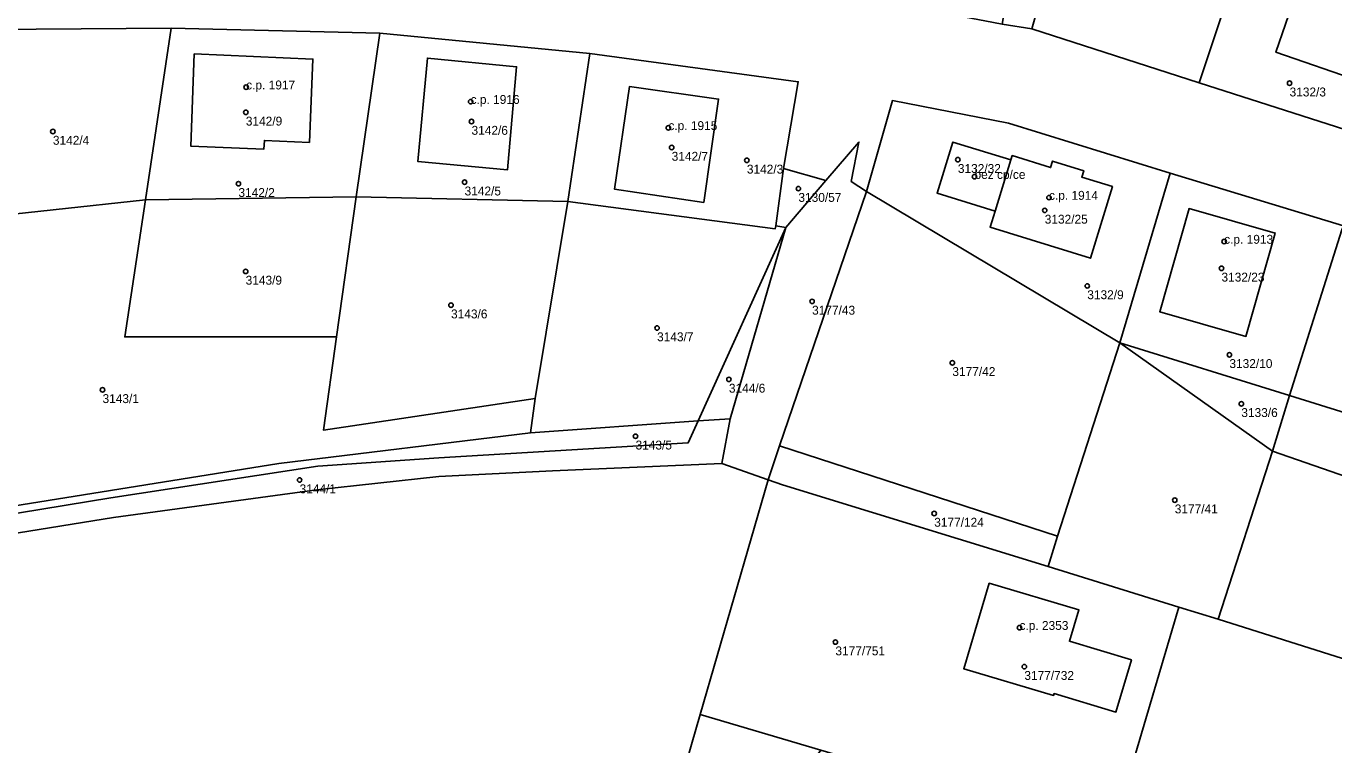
# Model space of a CAD drawing. Extents: x -878211 to -870363, y -1058464 to -1052522.
# Drawn here: x -874670.5 to -874523.6, y -1056692 to -1056611.2 of the extents above; entities that cross this region are included whole.
import ezdxf

# ---------------------------------------------------------------- set-up
doc = ezdxf.new("R2010")
doc.units = 0
for name, color, linetype in [('Definiční body', 7, 'Continuous'), ('Polygon budovy', 7, 'Continuous'), ('Polygon parcely', 7, 'Continuous')]:
    doc.layers.add(name, color=color, linetype=linetype)

msp = doc.modelspace()

# ---------------------------------------------------------------- linework, layer by layer
at = {"layer": 'Definiční body'}
for centre in [(-874645.82, -1056618.01994), (-874528.58, -1056617.56994), (-874620.6, -1056619.64994), (-874645.86, -1056620.83994), (-874667.54, -1056622.99994), (-874620.5, -1056621.87994), (-874598.38, -1056622.58994), (-874598.01, -1056624.79994), (-874589.56, -1056626.23994), (-874565.85, -1056626.16994), (-874646.69, -1056628.86994), (-874621.28, -1056628.69994), (-874563.98, -1056628.07994), (-874583.77, -1056629.41994), (-874556.09, -1056631.86994), (-874555.61, -1056630.42994), (-874535.93, -1056635.36994), (-874645.88, -1056638.72994), (-874536.23, -1056638.37994), (-874551.31, -1056640.35994), (-874582.23, -1056642.09994), (-874622.8, -1056642.51994), (-874599.65, -1056645.08994), (-874566.47, -1056648.99994), (-874535.34, -1056648.09994), (-874591.58, -1056650.86994), (-874661.96, -1056652.03994), (-874534, -1056653.60994), (-874602.07, -1056657.25994), (-874639.82, -1056662.17994), (-874541.48, -1056664.43994), (-874568.51, -1056665.93994), (-874558.93, -1056678.77994), (-874579.61, -1056680.39994), (-874558.38, -1056683.15994)]:
    msp.add_circle(centre, 0.25, dxfattribs=at)
at = {"layer": 'Polygon budovy'}
for points in [[(-874530.12, -1056614.09), (-874520.57, -1056617.36), (-874517.32, -1056607.88), (-874526.88, -1056604.61)], [(-874651.65, -1056614.27), (-874652.04, -1056624.63), (-874643.82, -1056624.98), (-874643.77, -1056624), (-874638.72, -1056624.23), (-874638.32, -1056614.85)], [(-874626.52, -1056626.39), (-874616.46, -1056627.32), (-874615.43, -1056615.72), (-874625.45, -1056614.75)], [(-874604.43, -1056629.49), (-874594.41, -1056630.97), (-874592.73, -1056619.36), (-874602.76, -1056617.95)], [(-874568.19, -1056629.94), (-874561.66, -1056631.95), (-874559.9, -1056626.17), (-874566.41, -1056624.18)], [(-874551.93, -1056628.13), (-874551.71, -1056627.42), (-874555.21, -1056626.33), (-874555.43, -1056627.05), (-874559.75, -1056625.71), (-874559.9, -1056626.17), (-874561.66, -1056631.95), (-874562.23, -1056633.77), (-874550.96, -1056637.25), (-874548.49, -1056629.19)], [(-874543.17, -1056643.26), (-874533.48, -1056646.03), (-874530.19, -1056634.41), (-874539.87, -1056631.66)], [(-874565.19, -1056683.4), (-874555.1, -1056686.39), (-874555.04, -1056686.19), (-874548.09, -1056688.26), (-874546.36, -1056682.4), (-874553.31, -1056680.3), (-874552.25, -1056676.78), (-874562.33, -1056673.78)]]:
    msp.add_lwpolyline(points, close=True, dxfattribs=at)
at = {"layer": 'Polygon parcely'}
for points in [[(-874546.14, -1056592.16), (-874550.37, -1056590.73), (-874559.16, -1056587.83), (-874559.58, -1056590.6), (-874559.85, -1056592.38), (-874557.82, -1056592.74), (-874560.87, -1056610.94), (-874557.53, -1056611.45), (-874553.66, -1056597.86), (-874552.14, -1056593.1), (-874545.38, -1056592.43)], [(-874545.38, -1056592.43), (-874552.14, -1056593.1), (-874553.66, -1056597.86), (-874557.53, -1056611.45), (-874538.75, -1056617.53), (-874531.91, -1056597.08)], [(-874519.44, -1056623.7), (-874513.29, -1056603.18), (-874527.34, -1056598.5), (-874531.91, -1056597.08), (-874538.75, -1056617.53)], [(-874526.88, -1056604.61), (-874530.12, -1056614.09), (-874520.57, -1056617.36), (-874517.32, -1056607.88)], [(-874526.88, -1056604.61), (-874517.32, -1056607.88), (-874520.57, -1056617.36), (-874530.12, -1056614.09)], [(-874654.24, -1056611.37), (-874674.5, -1056611.53), (-874677.93, -1056632.92), (-874657.15, -1056630.68)], [(-874630.82, -1056611.95), (-874654.24, -1056611.37), (-874657.15, -1056630.68), (-874633.46, -1056630.33)], [(-874609.69, -1056630.88), (-874607.22, -1056614.22), (-874630.82, -1056611.95), (-874633.46, -1056630.33)], [(-874651.65, -1056614.27), (-874652.04, -1056624.63), (-874643.82, -1056624.98), (-874643.77, -1056624), (-874638.72, -1056624.23), (-874638.32, -1056614.85)], [(-874651.65, -1056614.27), (-874638.32, -1056614.85), (-874638.72, -1056624.23), (-874643.77, -1056624), (-874643.82, -1056624.98), (-874652.04, -1056624.63)], [(-874625.45, -1056614.75), (-874615.43, -1056615.72), (-874616.46, -1056627.32), (-874626.52, -1056626.39)], [(-874625.45, -1056614.75), (-874626.52, -1056626.39), (-874616.46, -1056627.32), (-874615.43, -1056615.72)], [(-874609.69, -1056630.88), (-874586.37, -1056633.94), (-874586.32, -1056633.6), (-874585.46, -1056627.16), (-874583.78, -1056617.4), (-874607.22, -1056614.22)], [(-874594.41, -1056630.97), (-874604.43, -1056629.49), (-874602.76, -1056617.95), (-874592.73, -1056619.36)], [(-874594.41, -1056630.97), (-874592.73, -1056619.36), (-874602.76, -1056617.95), (-874604.43, -1056629.49)], [(-874542.01, -1056627.68), (-874560.17, -1056622.07), (-874573.21, -1056619.53), (-874576.13, -1056629.76), (-874547.67, -1056646.74)], [(-874587.18, -1056662.15), (-874585.89, -1056658.34), (-874576.13, -1056629.76), (-874577.84, -1056628.61), (-874576.97, -1056624.18), (-874580.67, -1056628.5), (-874585.2, -1056633.78), (-874591.42, -1056655.29), (-874592.37, -1056660.31)], [(-874555.43, -1056627.05), (-874555.21, -1056626.33), (-874551.71, -1056627.42), (-874551.93, -1056628.13), (-874548.49, -1056629.19), (-874550.96, -1056637.25), (-874562.23, -1056633.77), (-874561.66, -1056631.95), (-874568.19, -1056629.94), (-874566.41, -1056624.18), (-874559.9, -1056626.17), (-874559.75, -1056625.71)], [(-874559.9, -1056626.17), (-874566.41, -1056624.18), (-874568.19, -1056629.94), (-874561.66, -1056631.95)], [(-874559.9, -1056626.17), (-874561.66, -1056631.95), (-874562.23, -1056633.77), (-874550.96, -1056637.25), (-874548.49, -1056629.19), (-874551.93, -1056628.13), (-874551.71, -1056627.42), (-874555.21, -1056626.33), (-874555.43, -1056627.05), (-874559.75, -1056625.71)], [(-874585.46, -1056627.16), (-874586.32, -1056633.6), (-874585.2, -1056633.78), (-874580.67, -1056628.5)], [(-874547.67, -1056646.74), (-874528.58, -1056652.68), (-874522.69, -1056634.07), (-874522.52, -1056633.61), (-874542.01, -1056627.68)], [(-874576.13, -1056629.76), (-874585.89, -1056658.34), (-874554.65, -1056668.48), (-874547.67, -1056646.74)], [(-874637.15, -1056656.56), (-874635.67, -1056646.07), (-874659.47, -1056646.09), (-874657.15, -1056630.68), (-874677.93, -1056632.92), (-874683.06, -1056666.87), (-874642.16, -1056660.32), (-874613.87, -1056656.86), (-874613.33, -1056653.02)], [(-874657.15, -1056630.68), (-874659.47, -1056646.09), (-874635.67, -1056646.07), (-874633.46, -1056630.33)], [(-874633.46, -1056630.33), (-874635.67, -1056646.07), (-874637.15, -1056656.56), (-874613.33, -1056653.02), (-874609.69, -1056630.88)], [(-874586.32, -1056633.6), (-874586.37, -1056633.94), (-874609.69, -1056630.88), (-874613.33, -1056653.02), (-874613.87, -1056656.86), (-874595.04, -1056655.54), (-874585.2, -1056633.78)], [(-874539.87, -1056631.66), (-874543.17, -1056643.26), (-874533.48, -1056646.03), (-874530.19, -1056634.41)], [(-874539.87, -1056631.66), (-874530.19, -1056634.41), (-874533.48, -1056646.03), (-874543.17, -1056643.26)], [(-874585.2, -1056633.78), (-874595.04, -1056655.54), (-874591.42, -1056655.29)], [(-874509.49, -1056658.62), (-874503.66, -1056639.59), (-874522.52, -1056633.61), (-874522.69, -1056634.07), (-874528.58, -1056652.68)], [(-874541.03, -1056676.46), (-874536.59, -1056677.84), (-874530.51, -1056658.93), (-874547.67, -1056646.74), (-874554.65, -1056668.48), (-874555.7, -1056671.89)], [(-874547.67, -1056646.74), (-874530.51, -1056658.93), (-874528.58, -1056652.68)], [(-874528.58, -1056652.68), (-874530.51, -1056658.93), (-874511.82, -1056665.4), (-874509.49, -1056658.62)], [(-874595.04, -1056655.54), (-874613.87, -1056656.86), (-874642.16, -1056660.32), (-874683.06, -1056666.87), (-874694.93, -1056668.88), (-874694.57, -1056669.7), (-874661.04, -1056664.2), (-874637.76, -1056660.62), (-874624.16, -1056659.67), (-874596.15, -1056657.99)], [(-874637.88, -1056663.27), (-874624.16, -1056661.77), (-874611.39, -1056661.13), (-874592.37, -1056660.31), (-874591.42, -1056655.29), (-874595.04, -1056655.54), (-874596.15, -1056657.99), (-874624.16, -1056659.67), (-874637.76, -1056660.62), (-874661.04, -1056664.2), (-874694.57, -1056669.7), (-874692.18, -1056677.02), (-874684.42, -1056670.21), (-874660.73, -1056666.41)], [(-874555.7, -1056671.89), (-874554.65, -1056668.48), (-874585.89, -1056658.34), (-874587.18, -1056662.15), (-874585.54, -1056662.73)], [(-874536.59, -1056677.84), (-874517.53, -1056683.84), (-874511.82, -1056665.4), (-874530.51, -1056658.93)], [(-874556.32, -1056699.93), (-874548.64, -1056702.2), (-874541.03, -1056676.46), (-874555.7, -1056671.89), (-874585.54, -1056662.73), (-874587.18, -1056662.15), (-874594.8, -1056688.54), (-874581.25, -1056692.55)], [(-874562.33, -1056673.78), (-874552.25, -1056676.78), (-874553.31, -1056680.3), (-874546.36, -1056682.4), (-874548.09, -1056688.26), (-874555.04, -1056686.19), (-874555.1, -1056686.39), (-874565.19, -1056683.4)], [(-874562.33, -1056673.78), (-874565.19, -1056683.4), (-874555.1, -1056686.39), (-874555.04, -1056686.19), (-874548.09, -1056688.26), (-874546.36, -1056682.4), (-874553.31, -1056680.3), (-874552.25, -1056676.78)], [(-874520.36, -1056710.57), (-874519.51, -1056707.69), (-874514.47, -1056705.1), (-874517.18, -1056699.85), (-874512.89, -1056685.34), (-874517.53, -1056683.84), (-874536.59, -1056677.84), (-874541.03, -1056676.46), (-874548.64, -1056702.2)], [(-874581.25, -1056692.55), (-874594.8, -1056688.54), (-874601.43, -1056711.5), (-874596.25, -1056713.03)]]:
    msp.add_lwpolyline(points, close=True, dxfattribs=at)
for points in [[(-874519.44, -1056623.7), (-874538.75, -1056617.53), (-874557.53, -1056611.45), (-874560.87, -1056610.94), (-874562.84, -1056610.56), (-874582.56, -1056606.78), (-874585.79, -1056606.36), (-874602.05, -1056603.32), (-874622.11, -1056601.39), (-874640.68, -1056600.17), (-874659.41, -1056600.63), (-874675.1, -1056600.84)], [(-874674.5, -1056611.53), (-874654.24, -1056611.37), (-874630.82, -1056611.95), (-874607.22, -1056614.22), (-874583.78, -1056617.4), (-874585.46, -1056627.16), (-874580.67, -1056628.5), (-874576.97, -1056624.18), (-874577.84, -1056628.61), (-874576.13, -1056629.76), (-874573.21, -1056619.53), (-874560.17, -1056622.07), (-874542.01, -1056627.68), (-874522.52, -1056633.61), (-874503.66, -1056639.59), (-874484.66, -1056645.64), (-874465.47, -1056651.46), (-874446.38, -1056657.11), (-874427.04, -1056662.88), (-874410.86, -1056667.5), (-874394.94, -1056671.52)], [(-874571.25, -1056835.31), (-874572.2, -1056826.32), (-874576.45, -1056826.41), (-874578.08, -1056824.19), (-874578.76, -1056805.25), (-874579.46, -1056785.71), (-874588.31, -1056763.12), (-874588.86, -1056762.3), (-874609.61, -1056731.29), (-874605.53, -1056725.7), (-874601.99, -1056713.43), (-874601.43, -1056711.5), (-874594.8, -1056688.54), (-874587.18, -1056662.15), (-874592.37, -1056660.31), (-874611.39, -1056661.13), (-874624.16, -1056661.77), (-874637.88, -1056663.27), (-874660.73, -1056666.41), (-874684.42, -1056670.21)]]:
    msp.add_lwpolyline(points, dxfattribs=at)

# ---------------------------------------------------------------- texts
at = {"layer": 'Definiční body'}
for s, p in [('c.p. 1917', (-874645.82, -1056618.27)), ('3132/3', (-874528.58, -1056619.059)), ('c.p. 1916', (-874620.6, -1056619.899)), ('3142/9', (-874645.86, -1056622.329)), ('3142/6', (-874620.5, -1056623.369)), ('c.p. 1915', (-874598.38, -1056622.84)), ('3142/4', (-874667.54, -1056624.489)), ('3142/7', (-874598.01, -1056626.289)), ('3142/3', (-874589.56, -1056627.729)), ('3132/32', (-874565.85, -1056627.659)), ('bez cp/ce', (-874563.98, -1056628.33)), ('3142/2', (-874646.69, -1056630.359)), ('3142/5', (-874621.28, -1056630.189)), ('3130/57', (-874583.77, -1056630.909)), ('c.p. 1914', (-874555.61, -1056630.679)), ('3132/25', (-874556.09, -1056633.359)), ('c.p. 1913', (-874535.93, -1056635.62)), ('3132/23', (-874536.23, -1056639.869)), ('3143/9', (-874645.88, -1056640.219)), ('3132/9', (-874551.31, -1056641.849)), ('3143/6', (-874622.8, -1056644.009)), ('3177/43', (-874582.23, -1056643.589)), ('3143/7', (-874599.65, -1056646.579)), ('3132/10', (-874535.34, -1056649.589)), ('3177/42', (-874566.47, -1056650.489)), ('3144/6', (-874591.58, -1056652.359)), ('3143/1', (-874661.96, -1056653.529)), ('3133/6', (-874534, -1056655.099)), ('3143/5', (-874602.07, -1056658.749)), ('3144/1', (-874639.82, -1056663.669)), ('3177/41', (-874541.48, -1056665.929)), ('3177/124', (-874568.51, -1056667.429)), ('c.p. 2353', (-874558.93, -1056679.03)), ('3177/751', (-874579.61, -1056681.889)), ('3177/732', (-874558.38, -1056684.649))]:
    msp.add_text(s, height=0.999996, dxfattribs=at).set_placement(p)

doc.saveas('drawing.dxf')
